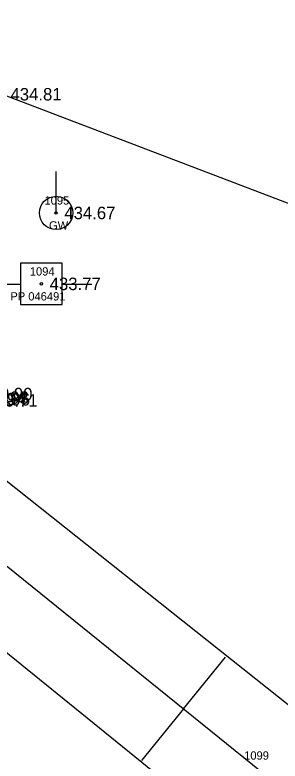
# Model space of a CAD drawing. Extents: x 1611865 to 1617004, y 775289 to 778546.
# Drawn here: x 1614492.7 to 1614524.5, y 777648.2 to 777738.1 of the extents above; entities that cross this region are included whole.
import ezdxf

# ---------------------------------------------------------------- set-up
doc = ezdxf.new("R2010")
doc.units = 0
for name, color, linetype in [('Default', 7, 'Continuous'), ('RD_EX_Road', 7, 'Continuous'), ('RD_EX_TX_Bridge_ELEV', 7, 'Continuous'), ('RD_EX_TX_Conc_ELEV', 7, 'Continuous'), ('RD_EX_TX_GuardRail_ELEV', 7, 'Continuous'), ('RD_EX_TX_UT_ELEV', 7, 'Continuous'), ('RD_EX_TX_VEG_ELEV', 7, 'Continuous'), ('RD_EX_UT', 7, 'Continuous'), ('RD_EX_UT_txCode', 7, 'Continuous'), ('RD_EX_VEG', 7, 'Continuous'), ('RD_HC_Cl', 7, 'Continuous'), ('RD_HC_Data_Tic', 7, 'Continuous'), ('RD_HC_Survey_ELEV', 7, 'Continuous'), ('RD_HC_Survey_txCode', 7, 'Continuous'), ('RD_SMD_Locator', 7, 'Continuous')]:
    doc.layers.add(name, color=color, linetype=linetype)

msp = doc.modelspace()

# ---------------------------------------------------------------- linework, layer by layer
at = {"layer": 'Default'}
msp.add_line((1614235.771, 777878.843), (1615250.563, 777057.494), dxfattribs=at)
at = {"layer": 'RD_EX_Road'}
for points in [[(1614484.146, 777687.927), (1614479.014, 777681.629), (1614474.139, 777675.502), (1614516.402, 777641.229), (1614565.544, 777600.816), (1614593.956, 777577.927), (1614671.57, 777514.586), (1614748.82, 777451.937), (1614826.225, 777388.927), (1614903.915, 777325.971), (1614945.384, 777292.004), (1614981.733, 777262.806), (1615059.733, 777200.116)], [(1614484.146, 777687.927), (1614527.248, 777653.669), (1614604.966, 777591.413), (1614629.131, 777572.935), (1614683.141, 777529.853), (1614759.905, 777466.847), (1614838.214, 777403.779), (1614915.189, 777340.175), (1614934.979, 777324.495), (1615070.79, 777214.661)]]:
    msp.add_lwpolyline(points, dxfattribs=at)
at = {"layer": 'RD_EX_UT'}
for p, q in [((1614497.604, 777714.22), (1614497.604, 777719.22)), ((1614498.333, 777708.193), (1614493.333, 777708.193)), ((1614493.333, 777708.193), (1614493.333, 777703.193)), ((1614498.333, 777703.193), (1614498.333, 777708.193)), ((1614489.902, 777705.631), (1614493.371, 777705.631)), ((1614498.261, 777705.631), (1614501.902, 777705.631)), ((1614493.333, 777703.193), (1614498.333, 777703.193))]:
    msp.add_line(p, q, dxfattribs=at)
msp.add_circle((1614497.604, 777714.22), 1.999, dxfattribs=at)
at = {"layer": 'RD_EX_VEG'}
msp.add_lwpolyline([(1614491.137, 777728.504), (1614530.115, 777713.617), (1614552.514, 777682.013), (1614626.017, 777614.414), (1614703.99, 777552.849), (1614782.74, 777493.625), (1614860.243, 777426.798), (1615012.807, 777300.366), (1615089.651, 777237.197)], dxfattribs=at)
at = {"layer": 'RD_HC_Cl'}
msp.add_line((1614235.771, 777878.843), (1615250.563, 777057.494), dxfattribs=at)
at = {"layer": 'RD_HC_Data_Tic'}
for q in [(1614517.953, 777660.743), (1614507.887, 777648.306)]:
    msp.add_line((1614512.92, 777654.525), q, dxfattribs=at)
at = {"layer": 'RD_SMD_Locator'}
for centre in [(1614497.604, 777714.22), (1614495.842, 777705.684)]:
    msp.add_circle(centre, 0.15, dxfattribs=at)

# ---------------------------------------------------------------- texts
at = {"layer": 'RD_EX_TX_Bridge_ELEV'}
msp.add_text('439.96', height=1.5, dxfattribs=at).set_placement((1614488.341, 777691.043))
msp.add_text('439.96', height=1.5, dxfattribs=at).set_placement((1614488.341, 777691.043))
at = {"layer": 'RD_EX_TX_Conc_ELEV'}
for s, p in [('440.93', (1614488.198, 777691.249)), ('440.90', (1614488.633, 777691.671))]:
    msp.add_text(s, height=1.5, dxfattribs=at).set_placement(p)
at = {"layer": 'RD_EX_TX_GuardRail_ELEV'}
for s, p in [('439.94', (1614487.822, 777691.081)), ('439.71', (1614489.257, 777690.903))]:
    msp.add_text(s, height=1.5, dxfattribs=at).set_placement(p)
at = {"layer": 'RD_EX_TX_UT_ELEV'}
msp.add_text('434.67', height=1.5, dxfattribs=at).set_placement((1614498.604, 777713.47))
at = {"layer": 'RD_EX_TX_VEG_ELEV'}
msp.add_text('434.81', height=1.5, dxfattribs=at).set_placement((1614492.137, 777727.754))
msp.add_text('434.81', height=1.5, dxfattribs=at).set_placement((1614492.137, 777727.754))
at = {"layer": 'RD_EX_UT_txCode'}
for s, p in [('1095', (1614496.218, 777715.22)), ('GW', (1614496.761, 777712.22)), ('1094', (1614494.456, 777706.684)), ('PP 046491', (1614492.117, 777703.684))]:
    msp.add_text(s, height=1, dxfattribs=at).set_placement(p)
at = {"layer": 'RD_HC_Survey_ELEV'}
msp.add_text('433.77', height=1.5, dxfattribs=at).set_placement((1614496.842, 777704.934))
at = {"layer": 'RD_HC_Survey_txCode'}
msp.add_text('1099', height=1, dxfattribs=at).set_placement((1614520.205, 777648.421))

doc.saveas('drawing.dxf')
